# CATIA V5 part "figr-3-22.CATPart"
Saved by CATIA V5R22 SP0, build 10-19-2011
Part number: Part1
Bounding box of the stored display mesh (mm): x -100.656 to 120.085, y -71.941 to 77.746, z 0 to 0
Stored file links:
  D:\Gaurav_V\CATIA V5-6R2012_manuscript\Gaurav_Catia\CATIA-V5-6R2012\catia_v5-6r2012_Prts\c03_catia_v5-6r2012_prt\figr-3-22.CATPart
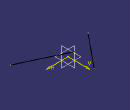
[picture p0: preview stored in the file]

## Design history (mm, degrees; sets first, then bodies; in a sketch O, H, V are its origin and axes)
Body1 (main body)
  Sketch1 on xy-plane, origin (0, 0, 0), H (1, 0, 0), V (0, 1, 0)
    line L1 (-9.7143, 77.7457) -> (-100.6564, -33.7935)
    line L2 (-27.4893, -3.1098) -> (120.0849, -71.9407)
